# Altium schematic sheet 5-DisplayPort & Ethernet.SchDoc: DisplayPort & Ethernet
size B; CompanyName: NGRF; Address1: 2130 Howard Drive W; Address2: North Mankato, MN 56003; Address3: www.nextgenrf.com; Revision: 2; SheetNumber: 5; SheetTotal: 7; ProjName: BytePipe X9002_HDK
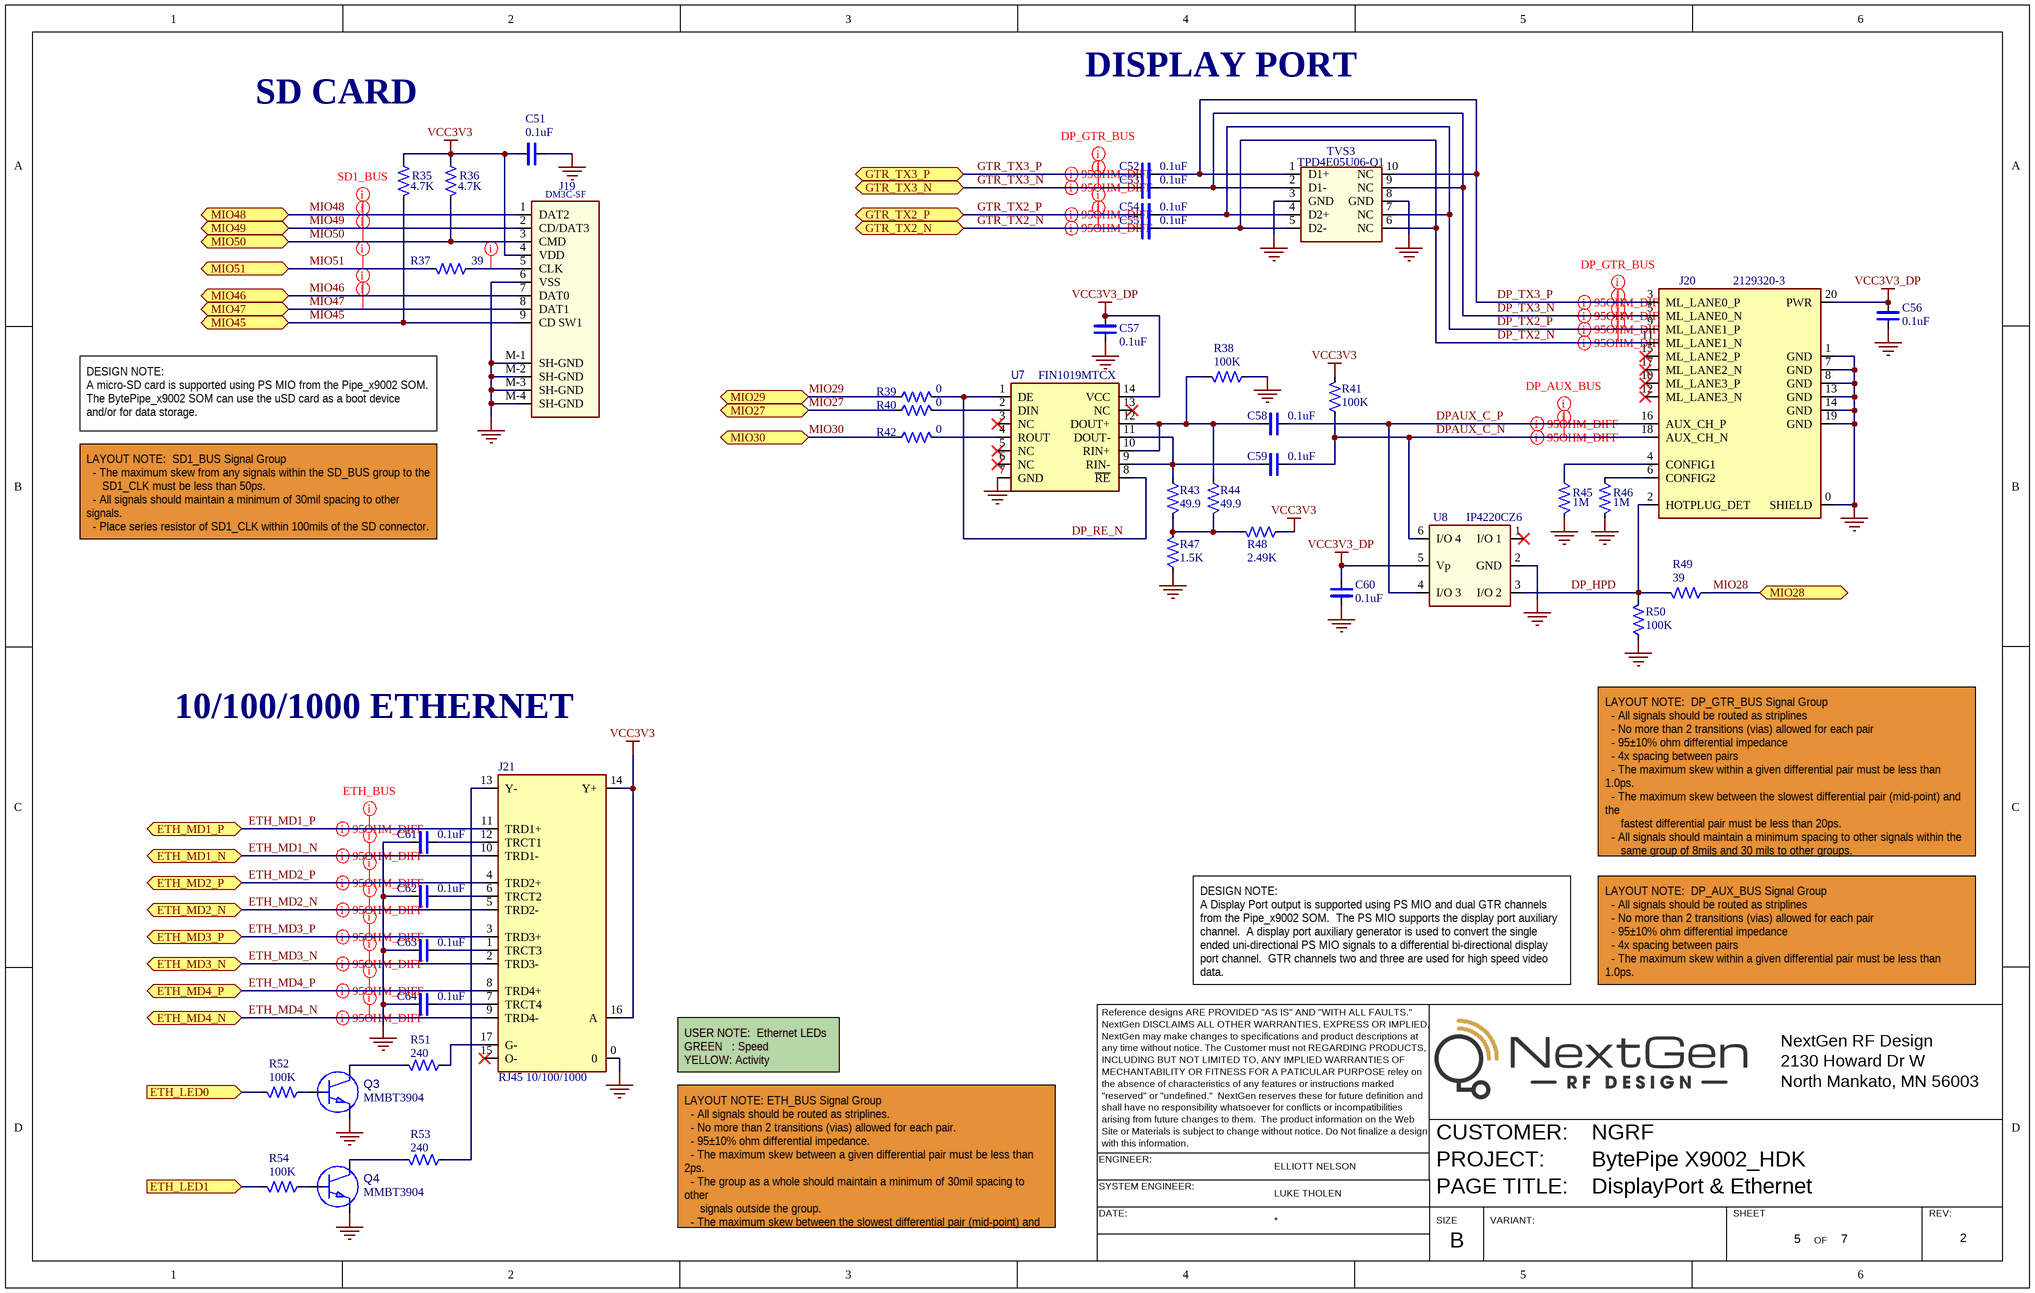
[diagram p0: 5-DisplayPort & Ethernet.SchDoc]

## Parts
C51  value 0.1uF  [SM/0402/CAP]  (hidden comment: CAP_CERAMIC_0402)
C52  value 0.1uF  [SM/0402/CAP]  (hidden comment: CAP_CERAMIC_0402)
C53  value 0.1uF  [SM/0402/CAP]  (hidden comment: CAP_CERAMIC_0402)
C54  value 0.1uF  [SM/0402/CAP]  (hidden comment: CAP_CERAMIC_0402)
C55  value 0.1uF  [SM/0402/CAP]  (hidden comment: CAP_CERAMIC_0402)
C56  value 0.1uF  [SM/0402/CAP]  (hidden comment: CAP_CERAMIC_0402)
C57  value 0.1uF  [SM/0402/CAP]  (hidden comment: CAP_CERAMIC_0402)
C58  value 0.1uF  [SM/0402/CAP]  (hidden comment: CAP_CERAMIC_0402)
C59  value 0.1uF  [SM/0402/CAP]  (hidden comment: CAP_CERAMIC_0402)
C60  value 0.1uF  [SM/0402/CAP]  (hidden comment: CAP_CERAMIC_0402)
C61  value 0.1uF  [SM/0402/CAP]  (hidden comment: CAP_CERAMIC_0402)
C62  value 0.1uF  [SM/0402/CAP]  (hidden comment: CAP_CERAMIC_0402)
C63  value 0.1uF  [SM/0402/CAP]  (hidden comment: CAP_CERAMIC_0402)
C64  value 0.1uF  [SM/0402/CAP]  (hidden comment: CAP_CERAMIC_0402)
J19  value DM3C-SF  [SM/CON/MICRO_SD-CARD/HOLDER]  (hidden comment: CONN MICRO SD CARD HINGED TYPE)
J20  value 2129320-3  [CON/TE/2129320-3]  (hidden comment: CON_TE_2129320-3)
J21  value RJ45 10/100/1000  [CON/RJ45/L829-1J1T-43]  (hidden comment: CON_RJ45_MagJack_L829-1J1T-43)
Q3  value MMBT3904  [SM/SOT23_A]  (hidden comment: TRANSISTOR_NPN_SOT23)
Q4  value MMBT3904  [SM/SOT23_A]  (hidden comment: TRANSISTOR_NPN_SOT23)
R35  value 4.7K  [SM/0402/RES]  (hidden comment: RES_0402_A)
R36  value 4.7K  [SM/0402/RES]  (hidden comment: RES_0402_A)
R37  value 39  [SM/0402/RES]  (hidden comment: RES_0402_A)
R38  value 100K  [SM/0402/RES]  (hidden comment: RES_0402_A)
R39  value 0  [SM/0402/RES]  (hidden comment: RES_0402_A)
R40  value 0  [SM/0402/RES]  (hidden comment: RES_0402_A)
R41  value 100K  [SM/0402/RES]  (hidden comment: RES_0402_A)
R42  value 0  [SM/0402/RES]  (hidden comment: RES_0402_A)
R43  value 49.9  [SM/0402/RES]  (hidden comment: RES_0402_A)
R44  value 49.9  [SM/0402/RES]  (hidden comment: RES_0402_A)
R45  value 1M  [SM/0402/RES]  (hidden comment: RES_0402_A)
R46  value 1M  [SM/0402/RES]  (hidden comment: RES_0402_A)
R47  value 1.5K  [SM/0402/RES]  (hidden comment: RES_0402_A)
R48  value 2.49K  [SM/0402/RES]  (hidden comment: RES_0402_A)
R49  value 39  [SM/0402/RES]  (hidden comment: RES_0402_A)
R50  value 100K  [SM/0402/RES]  (hidden comment: RES_0402_A)
R51  value 240  [SM/0402/RES]  (hidden comment: RES_0402_A)
R52  value 100K  [SM/0402/RES]  (hidden comment: RES_0402_A)
R53  value 240  [SM/0402/RES]  (hidden comment: RES_0402_A)
R54  value 100K  [SM/0402/RES]  (hidden comment: RES_0402_A)
TVS3  value TPD4E05U06-Q1  [SM/DFN10/2.5X1MM_A]  (hidden comment: TVS_TPD4E05U06_2.5mmX1mm)
U7  value FIN1019MTCX  [SM/TSSOP14_5X6.4MM_A]  (hidden comment: IC_FIN1019MTCX_TSSOP-14)
U8  value IP4220CZ6  [SM/TSOP-6_A]  (hidden comment: IC_IP4220CZ6_TSOP-6)

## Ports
ETH_LED0 (in), ETH_LED1 (in), ETH_MD1_N (bidir), ETH_MD1_P (bidir), ETH_MD2_N (bidir), ETH_MD2_P (bidir), ETH_MD3_N (bidir), ETH_MD3_P (bidir), ETH_MD4_N (bidir), ETH_MD4_P (bidir), GTR_TX2_N (bidir), GTR_TX2_P (bidir), GTR_TX3_N (bidir), GTR_TX3_P (bidir), MIO27 (bidir), MIO28 (bidir), MIO29 (bidir), MIO30 (bidir), MIO45 (bidir), MIO46 (bidir), MIO47 (bidir), MIO48 (bidir), MIO49 (bidir), MIO50 (bidir), MIO51 (bidir)

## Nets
GND: C51.2(N2) C56.2(N2) C57.2(N2) C60.2(N2) C61.1(N1) C62.1(N1) C63.1(N1) C64.1(N1) J19.6(VSS) J19.M-1(SH-GND) J19.M-2(SH-GND) J19.M-3(SH-GND) J19.M-4(SH-GND) J20.0(SHIELD) J20.1(GND) J20.7(GND) J20.8(GND) J20.13(GND) J20.14(GND) J20.19(GND) J21.0 Q3.2(E) Q4.2(E) R38.1 R45.2 R46.2 R47.1 R50.1 TVS3.3(GND) TVS3.8(GND) U7.7(GND) U8.2(GND)
VCC3V3: C51.1(N1) J19.4(VDD) J21.14(Y+) J21.16(A) R35.1 R36.1 R41.2 R48.1
VCC3V3_DP: C56.1(N1) C57.1(N1) C60.1(N1) J20.20(PWR) U7.14(VCC) U8.5(Vp)
DP_HPD: J20.2(HOTPLUG_DET) R49.2 R50.2 U8.3(I/O_2)
DP_RE_N: R39.1 U7.1(DE) U7.8(~{RE})
DP_TX2_N: C55.2(N2) J20.11(ML_LANE1_N) TVS3.5(D2-) TVS3.6(NC)
DP_TX2_P: C54.2(N2) J20.9(ML_LANE1_P) TVS3.4(D2+) TVS3.7(NC)
DP_TX3_N: C53.2(N2) J20.5(ML_LANE0_N) TVS3.2(D1-) TVS3.9(NC)
DP_TX3_P: C52.2(N2) J20.3(ML_LANE0_P) TVS3.1(D1+) TVS3.10(NC)
DPAUX_C_N: C59.2(N2) J20.18(AUX_CH_N) R41.1 U8.6(I/O_4)
DPAUX_C_P: C58.2(N2) J20.16(AUX_CH_P) U8.4(I/O_3)
ETH_LED0: R52.2 ; port ETH_LED0
ETH_LED1: R54.2 ; port ETH_LED1
ETH_MD1_N: J21.10(TRD1-) ; port ETH_MD1_N
ETH_MD1_P: J21.11(TRD1+) ; port ETH_MD1_P
ETH_MD2_N: J21.5(TRD2-) ; port ETH_MD2_N
ETH_MD2_P: J21.4(TRD2+) ; port ETH_MD2_P
ETH_MD3_N: J21.2(TRD3-) ; port ETH_MD3_N
ETH_MD3_P: J21.3(TRD3+) ; port ETH_MD3_P
ETH_MD4_N: J21.9(TRD4-) ; port ETH_MD4_N
ETH_MD4_P: J21.8(TRD4+) ; port ETH_MD4_P
GTR_TX2_N: C55.1(N1) ; port GTR_TX2_N
GTR_TX2_P: C54.1(N1) ; port GTR_TX2_P
GTR_TX3_N: C53.1(N1) ; port GTR_TX3_N
GTR_TX3_P: C52.1(N1) ; port GTR_TX3_P
MIO27: R40.2 ; port MIO27
MIO28: R49.1 ; port MIO28
MIO29: R39.2 ; port MIO29
MIO30: R42.2 ; port MIO30
MIO45: J19.9(CD_SW1) R35.2 ; port MIO45
MIO46: J19.7(DAT0) ; port MIO46
MIO47: J19.8(DAT1) ; port MIO47
MIO48: J19.1(DAT2) ; port MIO48
MIO49: J19.2(CD/DAT3) ; port MIO49
MIO50: J19.3(CMD) R36.2 ; port MIO50
MIO51: R37.2 ; port MIO51
NetC58_1: C58.1(N1) R38.2 R44.1 U7.10(RIN+) U7.12(DOUT+)
NetC59_1: C59.1(N1) R43.1 U7.9(RIN-) U7.11(DOUT-)
NetC61_2: C61.2(N2) J21.12(TRCT1)
NetC62_2: C62.2(N2) J21.6(TRCT2)
NetC63_2: C63.2(N2) J21.1(TRCT3)
NetC64_2: C64.2(N2) J21.7(TRCT4)
NetJ19_5: J19.5(CLK) R37.1
NetJ20_4: J20.4(CONFIG1) R45.1
NetJ20_6: J20.6(CONFIG2) R46.1
NetJ21_13: J21.13(Y-) R53.2
NetJ21_17: J21.17(G-) R51.2
NetQ3_1: Q3.1(B) R52.1
NetQ3_3: Q3.3(C) R51.1
NetQ4_1: Q4.1(B) R54.1
NetQ4_3: Q4.3(C) R53.1
NetR40_1: R40.1 U7.2(DIN)
NetR42_1: R42.1 U7.4(ROUT)
NetR43_2: R43.2 R44.2 R47.2 R48.2

Not connected (* = marked no-connect by the designer): J20 10(ML_LANE3_P)* 12(ML_LANE3_N)* 15(ML_LANE2_P)* 17(ML_LANE2_N)*; J21 15(O-)*; U7 3(NC)* 5(NC)* 6(NC)* 13(NC)*; U8 1(I/O_1)*

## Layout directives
net class DP_GTR_BUS: DP_TX2_N, DP_TX2_P, DP_TX3_N, DP_TX3_P, GTR_TX2_N, GTR_TX2_P, GTR_TX3_N, GTR_TX3_P
net class DP_AUX_BUS: DPAUX_C_N, DPAUX_C_P
differential pair; Impedance: 90 Ohms; differential pair class 95OHM_DIFF: DP_TX2_N, DP_TX2_P, DP_TX3_N, DP_TX3_P, DPAUX_C_N, DPAUX_C_P, ETH_MD1_N, ETH_MD1_P, ETH_MD2_N, ETH_MD2_P, ETH_MD3_N, ETH_MD3_P, ETH_MD4_N, ETH_MD4_P, GTR_TX2_N, GTR_TX2_P, GTR_TX3_N, GTR_TX3_P
net class ETH_BUS: ETH_MD1_N, ETH_MD1_P, ETH_MD2_N, ETH_MD2_P, ETH_MD3_N, ETH_MD3_P, ETH_MD4_N, ETH_MD4_P
net class SD1_BUS: MIO46, MIO47, MIO48, MIO49, MIO50, MIO51, NetJ19_5

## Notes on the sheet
- DISPLAY PORT
- SD CARD
- DESIGN NOTE:
  A micro-SD card is supported using PS MIO from the Pipe_x9002 SOM.  The BytePipe_x9002 SOM can use the uSD card as a boot device and/or for data storage.
- LAYOUT NOTE:  SD1_BUS Signal Group
  - The maximum skew from any signals within the SD_BUS group to the
  SD1_CLK must be less than 50ps.
  - All signals should maintain a minimum of 30mil spacing to other signals.
  - Place series resistor of SD1_CLK within 100mils of the SD connector.
  -MIO51 is SD1_CLK.
- 10/100/1000 ETHERNET
- (near R50) LAYOUT NOTE:  DP_GTR_BUS Signal Group
  - All signals should be routed as striplines
  - No more than 2 transitions (vias) allowed for each pair
  - 95±10% ohm differential impedance
  - 4x spacing between pairs
  - The maximum skew within a given differential pair must be less than 1.0ps.
  - The maximum skew between the slowest differential pair (mid-point) and the
  fastest differential pair must be less than 20ps.
  - All signals should maintain a minimum spacing to other signals within the
  same group of 8mils and 30 mils to other groups.
  - All signals within the group should be routed on the same layer.
- Reference designs ARE PROVIDED "AS IS" AND "WITH ALL FAULTS."
- NextGen DISCLAIMS ALL OTHER WARRANTIES, EXPRESS OR IMPLIED,
- NextGen may make changes to specifications and product descriptions at
- DESIGN NOTE:
  A Display Port output is supported using PS MIO and dual GTR channels from the Pipe_x9002 SOM.  The PS MIO supports the display port auxiliary channel.  A display port auxiliary generator is used to convert the single ended uni-directional PS MIO signals to a differential bi-directional display port channel.  GTR channels two and three are used for high speed video data.
- LAYOUT NOTE:  DP_AUX_BUS Signal Group
  - All signals should be routed as striplines
  - No more than 2 transitions (vias) allowed for each pair
  - 95±10% ohm differential impedance
  - 4x spacing between pairs
  - The maximum skew within a given differential pair must be less than 1.0ps.
- NextGen RF Design
- USER NOTE:  Ethernet LEDs
  GREEN   : Speed
  YELLOW: Activity
- any time without notice. The Customer must not REGARDING PRODUCTS,
- INCLUDING BUT NOT LIMITED TO, ANY IMPLIED WARRANTIES OF
- MECHANTABILITY OR FITNESS FOR A PATICULAR PURPOSE reley on
- "reserved" or "undefined."  NextGen reserves these for future definition and
- the absence of characteristics of any features or instructions marked
- shall have no responsibility whatsoever for conflicts or incompatibilities
- 2130 Howard Dr W
- North Mankato, MN 56003
- ENGINEER:
- Site or Materials is subject to change without notice. Do Not finalize a design
- with this information.
- arising from future changes to them.  The product information on the Web
- ELLIOTT NELSON
- CUSTOMER:
- PROJECT:
- LAYOUT NOTE: ETH_BUS Signal Group
  - All signals should be routed as striplines.
  - No more than 2 transitions (vias) allowed for each pair.
  - 95±10% ohm differential impedance.
  - The maximum skew between a given differential pair must be less than 2ps.
  - The group as a whole should maintain a minimum of 30mil spacing to other
  signals outside the group.
  - The maximum skew between the slowest differential pair (mid-point) and the
  fastest differential pair of the signal group must be less than 10ps.
- SYSTEM ENGINEER:
- DATE:
- LUKE THOLEN
- SIZE
- PAGE TITLE:
- VARIANT:
- SHEET
- OF
- REV:
- B

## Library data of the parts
C51-C64 = CAP_CERAMIC_0402: CAP CER 0.1UF 25V X7R 0402; TOL: ±10%; OEM#: CL05B104KA5NNNC; OEM NAME: Samsung
J19 = CON_HIROSE_MICRO-SD_HINGED: 10 (8 + 2) Position Card Connector Secure Digital - microSD™ Surface Mount, Right Angle Gold; OEM NAME: Hirose Electric Co Ltd
J20 = CON_TE_2129320-3: DisplayPort, Mini  Receptacle Connector 20 Position Through Hole, Right Angle..; OEM NAME: TE
J21 = CON_RJ45_MagJack_L829-1J1T-43: 1 Port RJ45 Magjack Connector Through Hole 10/100/1000 Base-T, AutoMDIX; OEM NAME: Bel Fuse Inc
Q3 Q4 = TRANSISTOR_NPN_SOT23: Bipolar (BJT) Transistor NPN 40V 200mA 300MHz 300mW Surface Mount SOT-23-3 (TO-236); OEM#: MMBT3904LT1G; OEM NAME: ON Semiconductor
R35 R36 = RES_0402_A: RES SMD 4.7K OHM 1% 1/10W 0402; OEM#: ERJ-2RKF4701X; OEM NAME: Panasonic
R37 R49 = RES_0402_A: RES SMD 39 OHM 1% 1/10W 0402; OEM#: ERJ-2RKF39R0X; OEM NAME: Panasonic
R38 R41 R50 R52 R54 = RES_0402_A: RES SMD 100K OHM 1% 1/10W 0402; OEM#: ERJ-2RKF1003X; OEM NAME: Panasonic
R39 R40 R42 = RES_0402_A: RES SMD 0 OHM JUMPER 1/10W 0402; OEM#: ERJ-2GE0R00X; OEM NAME: Panasonic; TOL: 1%
R43 R44 = RES_0402_A: RES 49.9 OHM 1% 1/10W 0402; OEM#: ERJ-2RKF49R9X; OEM NAME: Panasonic
R45 R46 = RES_0402_A: RES SMD 1M OHM 1% 1/10W 0402; OEM#: ERJ-2RKF1004X; OEM NAME: Panasonic
R47 = RES_0402_A: RES SMD 1.5K OHM 1% 1/10W 0402; OEM#: ERJ-2RKF1501X; OEM NAME: Panasonic
R48 = RES_0402_A: RES SMD 2.49K OHM 1% 1/10W 0402; OEM#: ERJ-2RKF2491X; OEM NAME: Panasonic
R51 R53 = RES_0402_A: RES SMD 240 OHM 1% 1/10W 0402; OEM#: ERJ-2RKF2400X; OEM NAME: Panasonic
TVS3 = TVS_TPD4E05U06_2.5mmX1mm: TVS DIODE 5.5V 14V 10SON; OEM NAME: TI
U7 = IC_FIN1019MTCX_TSSOP-14: 1/1 Transceiver Full LVDS 14-TSSOP; OEM NAME: ON Semiconductor
U8 = IC_IP4220CZ6_TSOP-6: Dual USB ESD Protection; OEM#: IP4220CZ6,125; OEM NAME: NXP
